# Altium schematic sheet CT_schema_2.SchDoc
size 461 x 327 mm
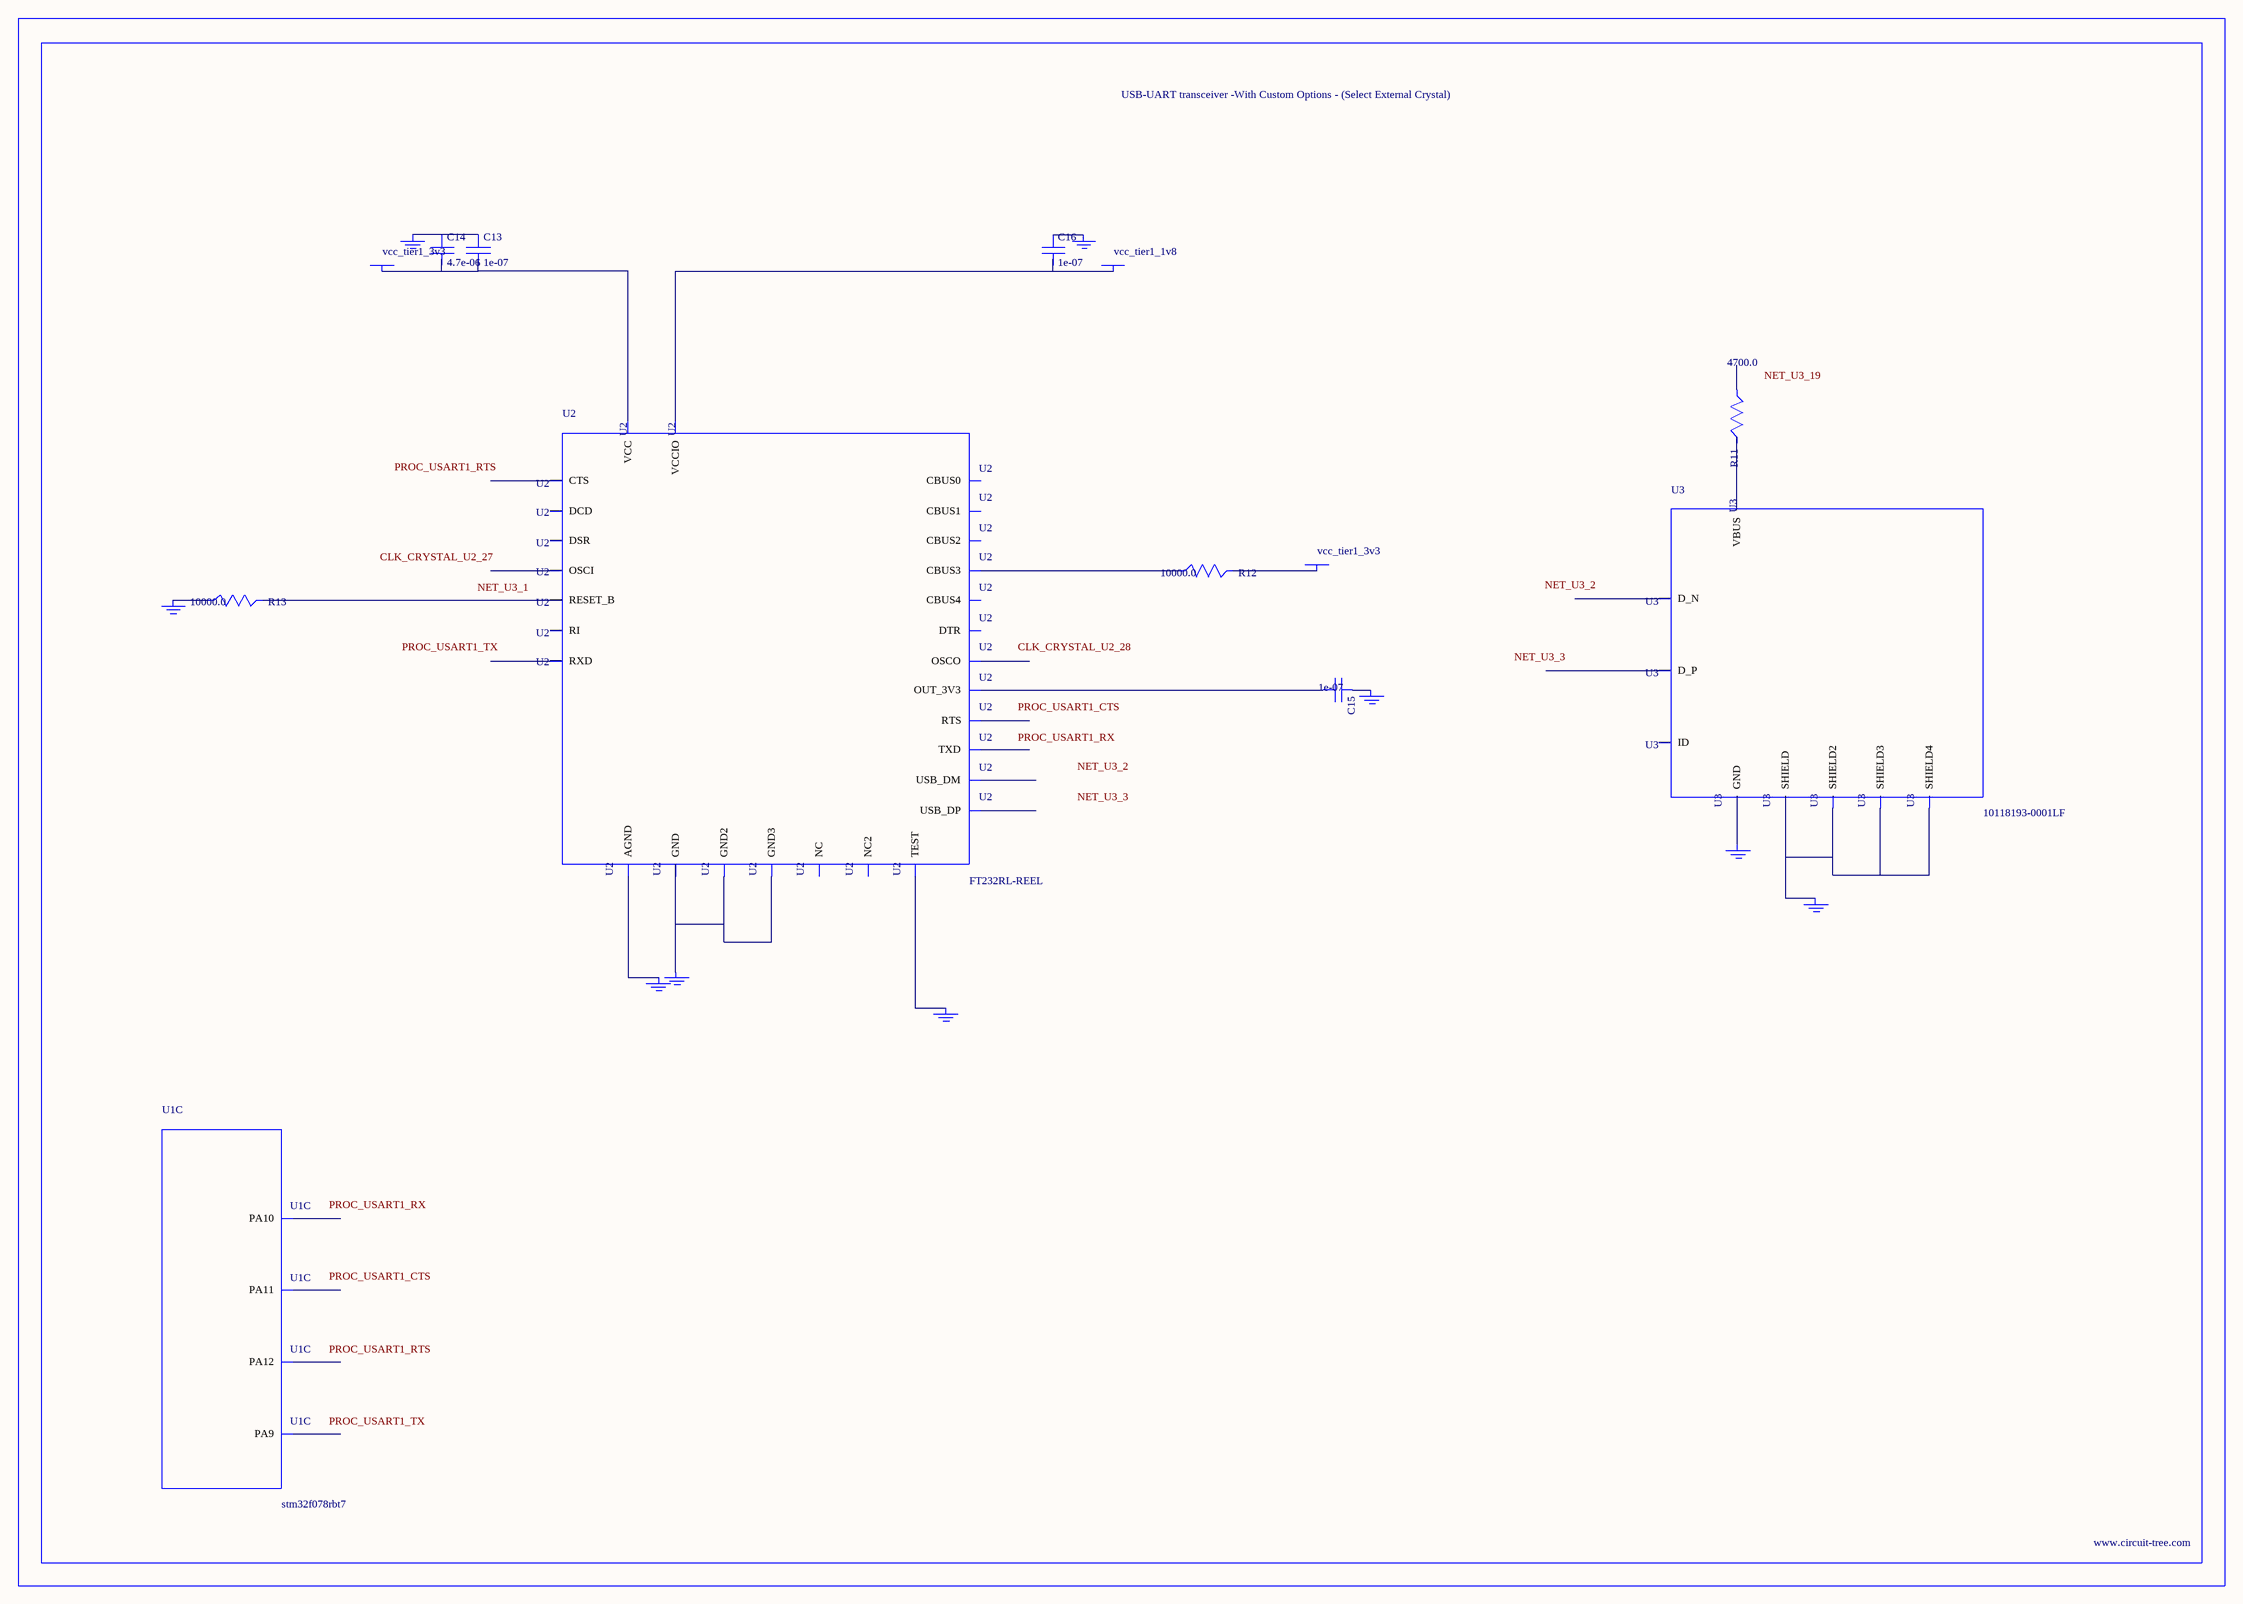
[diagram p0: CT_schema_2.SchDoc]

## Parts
BORDER1  (no value)
C13  1e-07  [C0402]
C14  4.7e-06  [C0805]
C15  1e-07  [C0402]
C16  1e-07  [C0402]
GND_INSTANCE_1_0  (no value)
GND_INSTANCE_1_1  (no value)
GND_INSTANCE_1_2  (no value)
GND_INSTANCE_1_3  (no value)
GND_INSTANCE_1_4  (no value)
GND_INSTANCE_1_5  (no value)
GND_INSTANCE_1_6  (no value)
GND_INSTANCE_1_7  (no value)
GND_INSTANCE_1_8  (no value)
POWER_INSTANCE_1_0  vcc_tier1_1v8
POWER_INSTANCE_1_1  vcc_tier1_3v3
POWER_INSTANCE_1_2  vcc_tier1_3v3
R11  4700.0  [R0603]
R12  10000.0  [R0603]
R13  10000.0  [R0603]
U1  stm32f078rbt7  [LQFP64]  (part C of 7)
U2  FT232RL-REEL  [SSOP-28]
U3  10118193-0001LF  [FCI_10118193-0001LF]

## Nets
NetC13_1: C13.1 C14.1 GND_INSTANCE_1_3.0(GND)
NetC13_2: C13.2 C14.2 POWER_INSTANCE_1_2.0(PWR) U2.20(VCC)
NetC15_1: C15.1 GND_INSTANCE_1_1.0(GND)
NetC15_2: C15.2 U2.17(OUT_3V3)
NetC16_1: C16.1 GND_INSTANCE_1_0.0(GND)
NetC16_2: C16.2 POWER_INSTANCE_1_0.0(PWR) U2.4(VCCIO)
NetGND_INSTANCE_1_2_0: GND_INSTANCE_1_2.0(GND) R13.1
NetGND_INSTANCE_1_4_0: GND_INSTANCE_1_4.0(GND) U2.25(AGND)
NetGND_INSTANCE_1_5_0: GND_INSTANCE_1_5.0(GND) U2.26(TEST)
NetGND_INSTANCE_1_6_0: GND_INSTANCE_1_6.0(GND) U2.7(GND) U2.18(GND2) U2.21(GND3)
NetGND_INSTANCE_1_7_0: GND_INSTANCE_1_7.0(GND) U3.6(SHIELD) U3.7(SHIELD2) U3.8(SHIELD3) U3.9(SHIELD4)
NetGND_INSTANCE_1_8_0: GND_INSTANCE_1_8.0(GND) U3.5(GND)
NetPOWER_INSTANCE_1_1_0: POWER_INSTANCE_1_1.0(PWR) R12.2
NetR11_2: R11.2 U3.1(VBUS)
NetR12_1: R12.1 U2.14(CBUS3)
NetR13_2: R13.2 U2.19(RESET_B)

Not connected (* = marked no-connect by the designer): R11 1; U1 42(PA9) 43(PA10) 44(PA11) 45(PA12); U2 1(TXD) 2(DTR) 3(RTS) 5(RXD) 6(RI) 8(NC) 9(DSR) 10(DCD) 11(CTS) 12(CBUS4) 13(CBUS2) 15(USB_DP) 16(USB_DM) 22(CBUS1) 23(CBUS0) 24(NC2) 27(OSCI) 28(OSCO); U3 2(D_N) 3(D_P) 4(ID)

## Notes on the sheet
- Labels drawn without touching a wire or pin: CLK_CRYSTAL_U2_27, CLK_CRYSTAL_U2_28, NET_U3_1, NET_U3_2, NET_U3_3, NET_U3_19, PROC_USART1_CTS, PROC_USART1_RTS, PROC_USART1_RX, PROC_USART1_TX

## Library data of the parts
BORDER1 = BORDER_PAGE1
C13 C15 C16 = C0402C104K3RACTU
C14 = C0805C475K4RACTU
GND_INSTANCE_1_0-GND_INSTANCE_1_8 = GND
POWER_INSTANCE_1_0-POWER_INSTANCE_1_2 = PWR
R11 = RC0603JR-074K7L
R12 R13 = RC0603JR-0710KL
